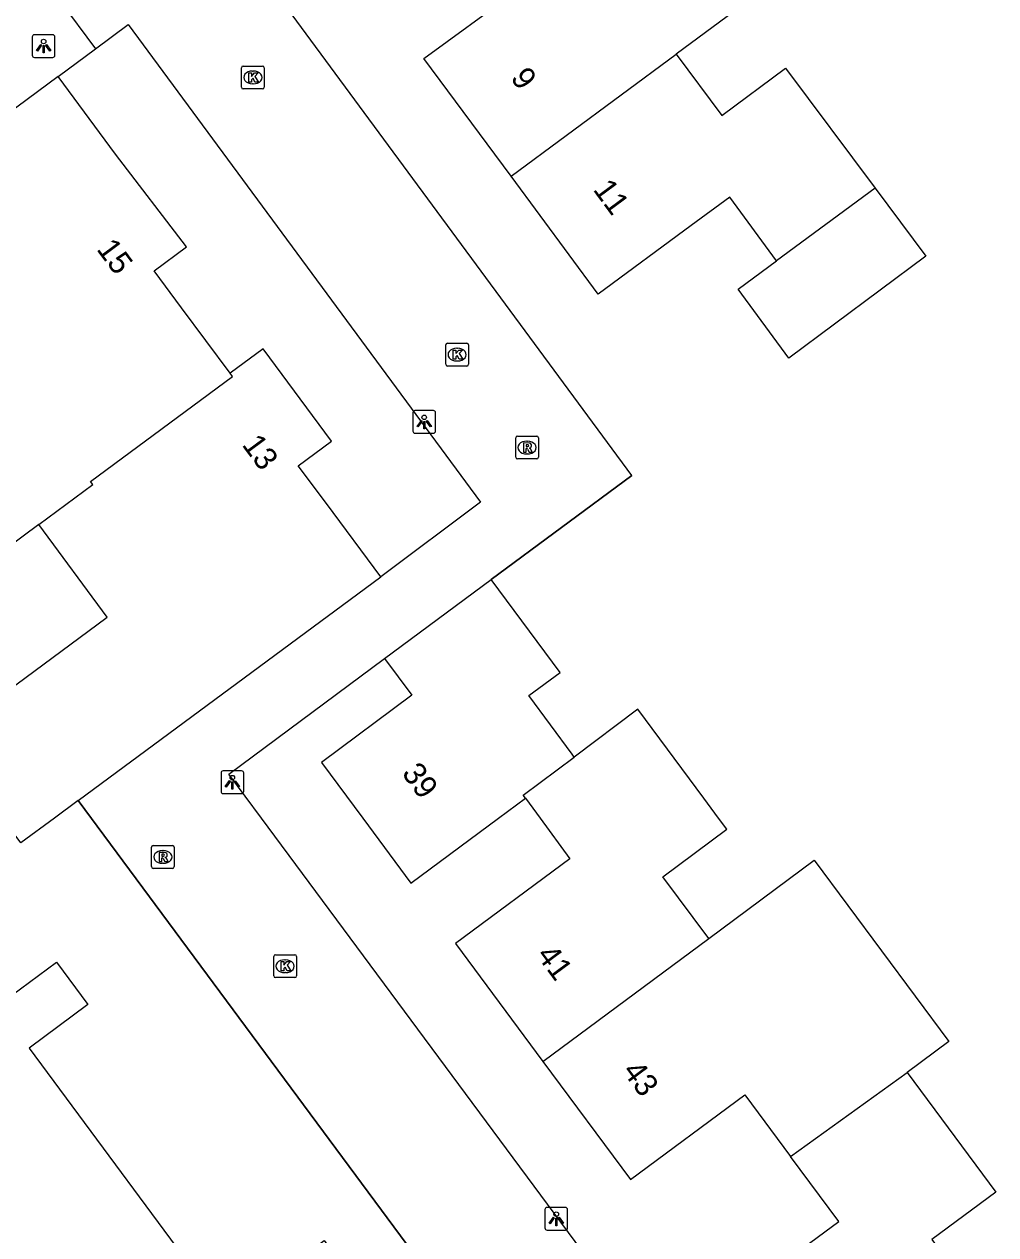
# Model space of a CAD drawing. Extents: x 163427 to 164190, y 380331 to 381641.
# Drawn here: x 163858.6 to 163901.2, y 381231.7 to 381284.8 of the extents above; entities that cross this region are included whole.
import ezdxf

# ---------------------------------------------------------------- set-up
doc = ezdxf.new("R2010")
doc.units = 0
for name, color, linetype in [('IMGEO_Kolk', 7, 'Continuous'), ('IMGEO_Lichtpunt', 7, 'Continuous'), ('IMGEO_Muur', 7, 'Continuous'), ('IMGEO_Pand', 7, 'Continuous'), ('IMGEO_Pand_nummerreeks', 7, 'Continuous'), ('IMGEO_Rioolput', 7, 'Continuous'), ('IMGEO_Voetpad_open', 7, 'Continuous')]:
    doc.layers.add(name, color=color, linetype=linetype)

msp = doc.modelspace()

# ---------------------------------------------------------------- linework, layer by layer
at = {"layer": 'IMGEO_Kolk'}
for p, q in [((163868.122, 381282.073), (163868.122, 381282.925)), ((163868.197, 381282.999), (163869.049, 381282.999)), ((163868.61, 381282.779), (163868.635, 381282.779)), ((163869.123, 381282.925), (163869.123, 381282.073)), ((163868.633, 381282.219), (163868.608, 381282.219)), ((163869.049, 381281.999), (163868.197, 381281.999)), ((163877.084, 381269.911), (163877.084, 381270.763)), ((163877.159, 381270.837), (163878.011, 381270.837)), ((163877.572, 381270.617), (163877.597, 381270.617)), ((163878.085, 381270.763), (163878.085, 381269.911)), ((163877.595, 381270.057), (163877.57, 381270.057)), ((163878.011, 381269.837), (163877.159, 381269.837)), ((163869.612, 381244), (163870.464, 381244)), ((163869.537, 381243.074), (163869.537, 381243.926)), ((163870.025, 381243.78), (163870.05, 381243.78)), ((163870.538, 381243.926), (163870.538, 381243.074)), ((163870.464, 381243), (163869.612, 381243)), ((163870.048, 381243.22), (163870.023, 381243.22))]:
    msp.add_line(p, q, dxfattribs=at)
for points in [[(163868.122, 381282.073), (163868.122, 381282.925)], [(163868.197, 381282.999), (163869.049, 381282.999)], [(163869.123, 381282.925), (163869.123, 381282.073)], [(163868.443, 381282.699), (163868.566, 381282.699), (163868.566, 381282.548), (163868.696, 381282.699), (163868.86, 381282.699), (163868.714, 381282.548), (163868.867, 381282.299), (163868.715, 381282.299), (163868.63, 381282.463), (163868.566, 381282.396), (163868.566, 381282.299), (163868.443, 381282.299), (163868.443, 381282.699)], [(163869.049, 381281.999), (163868.197, 381281.999)], [(163877.084, 381269.911), (163877.084, 381270.763)], [(163877.159, 381270.837), (163878.011, 381270.837)], [(163877.405, 381270.537), (163877.528, 381270.537), (163877.528, 381270.386), (163877.658, 381270.537), (163877.822, 381270.537), (163877.676, 381270.386), (163877.829, 381270.137), (163877.677, 381270.137), (163877.592, 381270.301), (163877.528, 381270.234), (163877.528, 381270.137), (163877.405, 381270.137), (163877.405, 381270.537)], [(163878.085, 381270.763), (163878.085, 381269.911)], [(163878.011, 381269.837), (163877.159, 381269.837)], [(163869.612, 381244), (163870.464, 381244)], [(163869.537, 381243.074), (163869.537, 381243.926)], [(163869.858, 381243.7), (163869.981, 381243.7), (163869.981, 381243.549), (163870.111, 381243.7), (163870.275, 381243.7), (163870.129, 381243.549), (163870.282, 381243.3), (163870.13, 381243.3), (163870.045, 381243.464), (163869.981, 381243.397), (163869.981, 381243.3), (163869.858, 381243.3), (163869.858, 381243.7)], [(163870.538, 381243.926), (163870.538, 381243.074)], [(163870.464, 381243), (163869.612, 381243)]]:
    msp.add_lwpolyline(points, dxfattribs=at)
for centre, start, end in [((163868.199, 381282.923), 91.552, 178.448), ((163868.199, 381282.923), 91.552, 178.448), ((163869.047, 381282.923), 1.552, 88.448), ((163869.047, 381282.923), 1.552, 88.448), ((163868.199, 381282.075), 181.552, 268.448), ((163868.199, 381282.075), 181.552, 268.448), ((163869.047, 381282.075), 271.552, 358.448), ((163869.047, 381282.075), 271.552, 358.448), ((163877.161, 381270.761), 91.552, 178.448), ((163877.161, 381270.761), 91.552, 178.448), ((163878.009, 381270.761), 1.552, 88.448), ((163878.009, 381270.761), 1.552, 88.448), ((163877.161, 381269.913), 181.552, 268.448), ((163877.161, 381269.913), 181.552, 268.448), ((163878.009, 381269.913), 271.552, 358.448), ((163878.009, 381269.913), 271.552, 358.448), ((163869.614, 381243.924), 91.552, 178.448), ((163869.614, 381243.924), 91.552, 178.448), ((163870.462, 381243.924), 1.552, 88.448), ((163870.462, 381243.924), 1.552, 88.448), ((163869.614, 381243.076), 181.552, 268.448), ((163869.614, 381243.076), 181.552, 268.448), ((163870.462, 381243.076), 271.552, 358.448), ((163870.462, 381243.076), 271.552, 358.448)]:
    msp.add_arc(centre, 0.0765, start, end, dxfattribs=at)
for centre, major_axis, ratio, start_param, end_param in [((163868.609, 381282.499), (-0.387, 0.002), 0.722429, 4.712389, 7.853982), ((163868.634, 381282.499), (-0.39, 0.002), 0.717154, 1.570796, 4.712389), ((163877.571, 381270.337), (-0.387, 0.002), 0.722429, 4.712389, 7.853982), ((163877.596, 381270.337), (-0.39, 0.002), 0.717154, 1.570796, 4.712389), ((163870.024, 381243.5), (-0.387, 0.002), 0.722429, 4.712389, 7.853982), ((163870.049, 381243.5), (-0.39, 0.002), 0.717154, 1.570796, 4.712389)]:
    msp.add_ellipse(centre, major_axis=major_axis, ratio=ratio, start_param=start_param, end_param=end_param, dxfattribs=at)
at = {"layer": 'IMGEO_Lichtpunt'}
for p, q in [((163859.844, 381284.376), (163859.036, 381284.376)), ((163859.844, 381284.376), (163859.036, 381284.376)), ((163858.942, 381284.281), (163858.942, 381283.474)), ((163858.942, 381284.281), (163858.942, 381283.474)), ((163859.938, 381283.474), (163859.938, 381284.281)), ((163859.938, 381283.474), (163859.938, 381284.281)), ((163859.036, 381283.38), (163859.844, 381283.38)), ((163859.036, 381283.38), (163859.844, 381283.38)), ((163876.544, 381267.883), (163875.736, 381267.883)), ((163876.544, 381267.883), (163875.736, 381267.883)), ((163875.642, 381267.788), (163875.642, 381266.981)), ((163875.642, 381267.788), (163875.642, 381266.981)), ((163876.638, 381266.981), (163876.638, 381267.788)), ((163876.638, 381266.981), (163876.638, 381267.788)), ((163875.736, 381266.887), (163876.544, 381266.887)), ((163875.736, 381266.887), (163876.544, 381266.887)), ((163867.225, 381251.978), (163867.225, 381251.171)), ((163867.225, 381251.978), (163867.225, 381251.171)), ((163868.127, 381252.073), (163867.319, 381252.073)), ((163868.127, 381252.073), (163867.319, 381252.073)), ((163868.221, 381251.171), (163868.221, 381251.978)), ((163868.221, 381251.171), (163868.221, 381251.978)), ((163867.319, 381251.077), (163868.127, 381251.077)), ((163867.319, 381251.077), (163868.127, 381251.077)), ((163881.435, 381232.82), (163881.435, 381232.013)), ((163881.435, 381232.82), (163881.435, 381232.013)), ((163882.337, 381232.915), (163881.529, 381232.915)), ((163882.337, 381232.915), (163881.529, 381232.915)), ((163882.431, 381232.013), (163882.431, 381232.82)), ((163882.431, 381232.013), (163882.431, 381232.82)), ((163881.529, 381231.919), (163882.337, 381231.919)), ((163881.529, 381231.919), (163882.337, 381231.919))]:
    msp.add_line(p, q, dxfattribs=at)
for points in [[(163859.316, 381283.945), (163859.355, 381283.917), (163859.167, 381283.655), (163859.129, 381283.682), (163859.316, 381283.945)], [(163859.418, 381283.897), (163859.465, 381283.897), (163859.465, 381283.575), (163859.418, 381283.575), (163859.418, 381283.897)], [(163859.528, 381283.917), (163859.566, 381283.944), (163859.753, 381283.682), (163859.714, 381283.654), (163859.528, 381283.917)], [(163876.016, 381267.452), (163876.055, 381267.424), (163875.867, 381267.162), (163875.829, 381267.189), (163876.016, 381267.452)], [(163876.118, 381267.404), (163876.165, 381267.404), (163876.165, 381267.082), (163876.118, 381267.082), (163876.118, 381267.404)], [(163876.228, 381267.424), (163876.266, 381267.451), (163876.453, 381267.189), (163876.414, 381267.161), (163876.228, 381267.424)], [(163867.599, 381251.642), (163867.638, 381251.614), (163867.45, 381251.352), (163867.412, 381251.379), (163867.599, 381251.642)], [(163867.701, 381251.594), (163867.748, 381251.594), (163867.748, 381251.272), (163867.701, 381251.272), (163867.701, 381251.594)], [(163867.811, 381251.614), (163867.849, 381251.641), (163868.036, 381251.379), (163867.997, 381251.351), (163867.811, 381251.614)], [(163881.809, 381232.484), (163881.848, 381232.456), (163881.66, 381232.194), (163881.622, 381232.221), (163881.809, 381232.484)], [(163881.911, 381232.436), (163881.958, 381232.436), (163881.958, 381232.114), (163881.911, 381232.114), (163881.911, 381232.436)], [(163882.021, 381232.456), (163882.059, 381232.483), (163882.246, 381232.221), (163882.207, 381232.193), (163882.021, 381232.456)]]:
    msp.add_lwpolyline(points, dxfattribs=at)
for centre in [(163859.441, 381284.079), (163876.141, 381267.586), (163867.724, 381251.776), (163881.934, 381232.618)]:
    msp.add_circle(centre, 0.0994, dxfattribs=at)
for centre, start, end in [((163859.036, 381284.281), 90, 180), ((163859.036, 381284.281), 90, 180), ((163859.844, 381284.281), 0, 90), ((163859.844, 381284.281), 0, 90), ((163859.036, 381283.474), 180, 270), ((163859.036, 381283.474), 180, 270), ((163859.844, 381283.474), 270, 0), ((163859.844, 381283.474), 270, 360), ((163875.736, 381267.788), 90, 180), ((163875.736, 381267.788), 90, 180), ((163876.544, 381267.788), 0, 90), ((163876.544, 381267.788), 0, 90), ((163875.736, 381266.981), 180, 270), ((163875.736, 381266.981), 180, 270), ((163876.544, 381266.981), 270, 0), ((163876.544, 381266.981), 270, 360), ((163867.319, 381251.978), 90, 180), ((163867.319, 381251.978), 90, 180), ((163868.127, 381251.978), 0, 90), ((163868.127, 381251.978), 0, 90), ((163867.319, 381251.171), 180, 270), ((163867.319, 381251.171), 180, 270), ((163868.127, 381251.171), 270, 0), ((163868.127, 381251.171), 270, 360), ((163881.529, 381232.82), 90, 180), ((163881.529, 381232.82), 90, 180), ((163882.337, 381232.82), 0, 90), ((163882.337, 381232.82), 0, 90), ((163881.529, 381232.013), 180, 270), ((163881.529, 381232.013), 180, 270), ((163882.337, 381232.013), 270, 0), ((163882.337, 381232.013), 270, 360)]:
    msp.add_arc(centre, 0.0946, start, end, dxfattribs=at)
at = {"layer": 'IMGEO_Muur'}
for points in [[(163885.244, 381265.036), (163879.085, 381260.472)], [(163860.96, 381250.771), (163877.641, 381228.227)]]:
    msp.add_lwpolyline(points, dxfattribs=at)
at = {"layer": 'IMGEO_Pand'}
for points in [[(163884.073, 381293.545), (163884.168, 381293.417), (163887.975, 381288.308), (163888.396, 381288.622), (163890.379, 381285.881), (163887.194, 381283.523)], [(163879.953, 381278.161), (163876.122, 381283.338), (163880.052, 381286.22), (163881.679, 381287.413), (163879.62, 381290.22), (163880.557, 381290.92)], [(163879.953, 381278.161), (163887.194, 381283.523)], [(163887.194, 381283.523), (163889.203, 381280.828), (163891.997, 381282.91), (163895.924, 381277.641)], [(163860.073, 381282.538), (163854.632, 381278.51)], [(163867.629, 381269.516), (163865.492, 381272.391), (163864.285, 381274.015), (163865.709, 381275.073), (163862.589, 381279.138), (163860.073, 381282.538)], [(163891.601, 381274.459), (163889.544, 381277.247), (163887.858, 381276.002), (163883.779, 381272.991), (163879.953, 381278.161)], [(163895.924, 381277.641), (163898.15, 381274.654), (163892.144, 381270.178), (163889.909, 381273.214), (163891.601, 381274.459)], [(163895.924, 381277.641), (163891.601, 381274.459)], [(163874.232, 381260.591), (163871.848, 381263.797), (163870.612, 381265.459), (163872.071, 381266.543), (163869.078, 381270.593), (163867.629, 381269.516)], [(163859.229, 381262.877), (163861.604, 381264.639), (163861.504, 381264.773), (163867.73, 381269.379), (163867.629, 381269.516)], [(163859.229, 381262.877), (163853.776, 381258.83)], [(163860.96, 381250.771), (163859.918, 381250), (163858.447, 381248.912), (163857.642, 381250), (163855.473, 381252.932), (163855.047, 381253.507), (163862.228, 381258.82), (163859.229, 381262.877)], [(163860.96, 381250.771), (163874.232, 381260.591)], [(163874.395, 381256.997), (163879.085, 381260.472)], [(163882.72, 381252.68), (163882.629, 381252.804), (163880.726, 381255.372), (163882.106, 381256.395), (163879.085, 381260.472)], [(163874.395, 381256.997), (163875.59, 381255.395), (163871.634, 381252.444), (163873.443, 381250), (163875.553, 381247.15), (163879.403, 381250), (163880.582, 381250.873)], [(163888.621, 381244.714), (163886.609, 381247.428), (163889.42, 381249.512), (163889.059, 381250), (163888.415, 381250.869), (163885.515, 381254.782), (163882.72, 381252.68)], [(163880.582, 381250.873), (163880.487, 381251.001), (163882.72, 381252.68)], [(163880.582, 381250.873), (163881.224, 381250), (163882.536, 381248.216), (163877.516, 381244.499), (163881.352, 381239.317)], [(163888.621, 381244.714), (163893.253, 381248.153), (163899.161, 381240.196), (163897.33, 381238.837)], [(163881.352, 381239.317), (163888.621, 381244.714)], [(163862.869, 381224.888), (163852.872, 381238.397), (163856.439, 381241.037), (163860.006, 381243.677), (163861.386, 381241.813), (163858.81, 381239.907), (163867.428, 381228.261), (163871.747, 381231.458), (163877.4, 381223.819), (163873.29, 381220.778), (163872.225, 381222.218), (163870.608, 381221.021), (163867.926, 381219.036), (163867.729, 381218.89), (163867.592, 381218.789)], [(163881.352, 381239.317), (163885.188, 381234.136), (163890.209, 381237.853), (163892.207, 381235.154)], [(163892.207, 381235.154), (163897.33, 381238.837)], [(163897.33, 381238.837), (163901.218, 381233.59), (163898.407, 381231.507), (163900.412, 381228.801)], [(163893.141, 381223.396), (163889.304, 381228.577), (163894.325, 381232.294), (163892.207, 381235.154)]]:
    msp.add_lwpolyline(points, dxfattribs=at)
at = {"layer": 'IMGEO_Rioolput'}
for p, q in [((163880.153, 381265.834), (163880.153, 381266.686)), ((163880.228, 381266.76), (163881.08, 381266.76)), ((163880.641, 381266.54), (163880.666, 381266.54)), ((163881.154, 381266.686), (163881.154, 381265.834)), ((163881.08, 381265.76), (163880.228, 381265.76)), ((163880.664, 381265.98), (163880.639, 381265.98)), ((163864.173, 381247.868), (163864.173, 381248.72)), ((163864.248, 381248.794), (163865.1, 381248.794)), ((163865.174, 381248.72), (163865.174, 381247.868)), ((163864.661, 381248.574), (163864.686, 381248.574)), ((163865.1, 381247.794), (163864.248, 381247.794)), ((163864.684, 381248.014), (163864.659, 381248.014))]:
    msp.add_line(p, q, dxfattribs=at)
for points in [[(163880.153, 381265.834), (163880.153, 381266.686)], [(163880.228, 381266.76), (163881.08, 381266.76)], [(163880.742, 381266.458), (163880.49, 381266.46), (163880.49, 381266.06)], [(163880.668, 381266.379), (163880.614, 381266.379), (163880.614, 381266.298)], [(163880.614, 381266.298), (163880.666, 381266.298)], [(163881.154, 381266.686), (163881.154, 381265.834)], [(163881.08, 381265.76), (163880.228, 381265.76)], [(163880.49, 381266.06), (163880.614, 381266.06), (163880.614, 381266.222), (163880.625, 381266.222)], [(163880.672, 381266.193), (163880.743, 381266.06), (163880.883, 381266.06), (163880.818, 381266.186)], [(163864.173, 381247.868), (163864.173, 381248.72)], [(163864.248, 381248.794), (163865.1, 381248.794)], [(163865.174, 381248.72), (163865.174, 381247.868)], [(163864.762, 381248.492), (163864.51, 381248.494), (163864.51, 381248.094)], [(163864.51, 381248.094), (163864.634, 381248.094), (163864.634, 381248.256), (163864.645, 381248.256)], [(163864.688, 381248.413), (163864.634, 381248.413), (163864.634, 381248.332)], [(163864.634, 381248.332), (163864.686, 381248.332)], [(163864.692, 381248.227), (163864.763, 381248.094), (163864.903, 381248.094), (163864.838, 381248.22)], [(163865.1, 381247.794), (163864.248, 381247.794)]]:
    msp.add_lwpolyline(points, dxfattribs=at)
for centre, radius, start, end in [((163880.23, 381266.684), 0.0765, 91.552, 178.448), ((163880.23, 381266.684), 0.0765, 91.552, 178.448), ((163880.65, 381266.487), 0.19, 274.7715, 282.9687), ((163880.674, 381266.283), 0.0964, 77.0061, 93.1865), ((163880.688, 381266.34), 0.0378, 276.6634, 79.6772), ((163880.741, 381266.348), 0.109, 350.3612, 89.416), ((163880.739, 381266.348), 0.112, 277.5842, 350.9817), ((163881.078, 381266.684), 0.0765, 1.552, 88.448), ((163881.078, 381266.684), 0.0765, 1.552, 88.448), ((163880.23, 381265.836), 0.0765, 181.552, 268.448), ((163880.23, 381265.836), 0.0765, 181.552, 268.448), ((163880.624, 381266.169), 0.0533, 26.0293, 88.6989), ((163880.723, 381266.133), 0.108, 29.5134, 73.7905), ((163881.078, 381265.836), 0.0765, 271.552, 358.448), ((163881.078, 381265.836), 0.0765, 271.552, 358.448), ((163864.25, 381248.718), 0.0765, 91.552, 178.448), ((163864.25, 381248.718), 0.0765, 91.552, 178.448), ((163865.098, 381248.718), 0.0765, 1.552, 88.448), ((163865.098, 381248.718), 0.0765, 1.552, 88.448), ((163864.644, 381248.203), 0.0533, 26.0293, 88.6989), ((163864.67, 381248.521), 0.19, 274.7715, 282.9687), ((163864.694, 381248.317), 0.0964, 77.0061, 93.1865), ((163864.708, 381248.374), 0.0378, 276.6634, 79.6772), ((163864.761, 381248.382), 0.109, 350.3612, 89.416), ((163864.759, 381248.382), 0.112, 277.5842, 350.9817), ((163864.743, 381248.167), 0.108, 29.5134, 73.7905), ((163864.25, 381247.87), 0.0765, 181.552, 268.448), ((163864.25, 381247.87), 0.0765, 181.552, 268.448), ((163865.098, 381247.87), 0.0765, 271.552, 358.448), ((163865.098, 381247.87), 0.0765, 271.552, 358.448)]:
    msp.add_arc(centre, radius, start, end, dxfattribs=at)
for centre, major_axis, ratio, start_param, end_param in [((163880.64, 381266.26), (-0.387, 0.002), 0.722429, 4.712389, 7.853982), ((163880.665, 381266.26), (-0.39, 0.002), 0.717154, 1.570796, 4.712389), ((163864.66, 381248.294), (-0.387, 0.002), 0.722429, 4.712389, 7.853982), ((163864.685, 381248.294), (-0.39, 0.002), 0.717154, 1.570796, 4.712389)]:
    msp.add_ellipse(centre, major_axis=major_axis, ratio=ratio, start_param=start_param, end_param=end_param, dxfattribs=at)
at = {"layer": 'IMGEO_Voetpad_open'}
for points in [[(163879.085, 381260.472), (163885.244, 381265.036), (163868.819, 381287.322), (163868.33, 381288.66), (163855.929, 381322.603)], [(163860.153, 381285.858), (163861.713, 381283.755)], [(163861.713, 381283.755), (163863.151, 381284.822), (163878.606, 381263.864), (163874.232, 381260.591)], [(163860.073, 381282.538), (163861.713, 381283.755)], [(163886.426, 381211.021), (163893.805, 381216.507), (163868.994, 381250), (163867.561, 381251.934), (163874.395, 381256.997)], [(163876.336, 381218.714), (163881.73, 381222.7), (163877.641, 381228.227), (163860.96, 381250.771)]]:
    msp.add_lwpolyline(points, dxfattribs=at)

# ---------------------------------------------------------------- texts
at = {"layer": 'IMGEO_Pand_nummerreeks'}
for s, rotation, p in [('9', 306.5029, (163879.898, 381282.471)), ('11', 306.5029, (163883.52, 381277.576)), ('15', 306.7092, (163861.736, 381274.961)), ('13', 306.4686, (163868.115, 381266.378)), ('39', 306.5087, (163875.126, 381251.959)), ('41', 306.5144, (163881.035, 381243.98)), ('43', 306.5135, (163884.804, 381238.89))]:
    msp.add_text(s, height=1, rotation=rotation, dxfattribs=at).set_placement(p)

doc.saveas('drawing.dxf')
